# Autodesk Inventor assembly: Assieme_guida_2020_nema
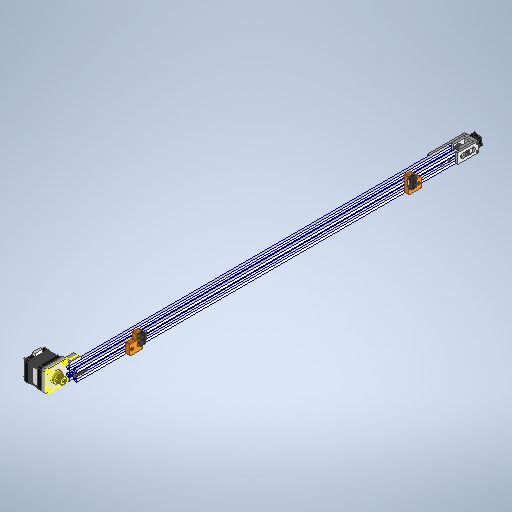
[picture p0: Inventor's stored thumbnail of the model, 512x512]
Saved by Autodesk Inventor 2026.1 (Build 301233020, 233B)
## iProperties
Created: 2026-01
Part Number: Assieme_guida_2020_nema
Document SubType Name: Assembly
Designer: hp
Sending System: Autodesk Inventor 2025
Preprocessor: ST-DEVELOPER v20
Title: Assieme_guida_2020_nema.stp
Author: R5800u
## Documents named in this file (17)
- C:\Users\hp\Documents\Inventor\DOM1_CartesianRobot\Assieme_guida_2020_nema - Copy.iam
- C:\Users\hp\Documents\Inventor\DOM1_CartesianRobot\2020 Belt Tensioner G_K.iam
- C:\Users\hp\Documents\Inventor\DOM1_CartesianRobot\GT2_20T.ipt
- C:\Users\hp\Documents\Inventor\DOM1_CartesianRobot\NO-NC Limit Switch.ipt
- C:\Users\hp\Documents\Inventor\DOM1_CartesianRobot\blocco_sensore.ipt
- C:\Users\hp\Documents\Inventor\DOM1_CartesianRobot\blocco_sensore_MIR.ipt
- C:\Users\hp\Documents\Inventor\DOM1_CartesianRobot\NEMA 42SHDC3030Z.ipt
- C:\Users\hp\Documents\Inventor\DOM1_CartesianRobot\blocco_nema.ipt
- C:\Users\hp\Documents\Inventor\DOM1_CartesianRobot\2020v2.ipt
- C:\Users\hp\Documents\Inventor\Content Center Files\R2026\en-US\ISO 4762(2)\ISO 4762 - M4 x 25ISO.ipt
- C:\Users\hp\Documents\Inventor\Content Center Files\R2026\en-US\ISO 4762(2)\ISO 4762 - M3 x 25ISO.ipt
- C:\Users\hp\Documents\Inventor\Content Center Files\R2021\en-US\ISO 4017(1)\ISO 4017 - M2 x 8 - ISO.ipt
- C:\Users\hp\Documents\Inventor\Content Center Files\R2026\en-US\ISO 4017(1)\ISO 4017 - M4 x 25 - ISO.ipt
- C:\Users\hp\Documents\Inventor\DOM1_CartesianRobot\2020 M4 (1).ipt
- C:\Users\hp\Documents\Inventor\Content Center Files\R2026\en-US\ANSI B18.3.1M(5)\ANSI B18.3.1M - M3x0.5 x 45(3).ipt
- C:\Users\hp\Documents\Inventor\Content Center Files\R2026\en-US\ISO 4032(2)\ISO 4032 - M3 - ISO.ipt
- C:\Users\hp\Documents\Inventor\DOM1_CartesianRobot\2020 M3.ipt
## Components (33 placed, 16 different names)
1. 2020:1
2. 2020 Belt Tensioner G_K:1 [sub-assembly]
3. GT2_20T:1 — Rigid:1
4. NO-NC Limit Switch:1 — Mate:9, Mate:10, Mate:11, Mate:36, Mate:37, Mate:38, Mate:39
5. NO-NC Limit Switch:2 — Mate:17, Mate:18, Mate:19
6. blocco_sensore:1
7. blocco_sensore_MIR:1
8. NEMA 42SHDC3030Z:1
9. blocco_nema:1
10. ISO 4762 M3 x 25:1 — Mate:32, Mate:33, Mate:76
11. ISO 4762 M3 x 25:2 — Mate:34, Mate:35, Mate:77
12. ISO 4017 M2 x 8:1 — Mate:36, Mate:37
13. ISO 4017 M2 x 8:2 — Mate:38, Mate:39
14. ISO 4017 M4 x 25:1 — Mate:40, Mate:41
15. ISO 4017 M4 x 25:2 — Mate:42, Mate:43
16. 2020 M4 (1):1 — Mate:44, Angle:1, Mate:51
17. 2020 M4 (1):2 — Mate:45, Angle:2, Mate:50
18. ISO 4762 M4 x 25:1 — Mate:46, Mate:47, Mate:50
19. ISO 4762 M4 x 25:2 — Mate:48, Mate:49, Mate:51
20. Drilled Forged Hexagon Socket Head Cap Screw - 6 Holes - Metric M3x0.5 x 45:1 — Mate:52, Mate:53
21. ISO 4032 M3:1 — Mate:60, Mate:61
22. Drilled Forged Hexagon Socket Head Cap Screw - 6 Holes - Metric M3x0.5 x 45:2 — Mate:54, Mate:55
23. Drilled Forged Hexagon Socket Head Cap Screw - 6 Holes - Metric M3x0.5 x 45:3 — Mate:56, Mate:57
24. Drilled Forged Hexagon Socket Head Cap Screw - 6 Holes - Metric M3x0.5 x 45:4 — Mate:58, Mate:59
25. ISO 4032 M3:2 — Mate:62, Mate:63
26. ISO 4032 M3:3 — Mate:64, Mate:65
27. ISO 4032 M3:4 — Mate:66, Mate:67
28. ISO 4762 M3 x 25:3 — Mate:68, Mate:69, Mate:79
29. ISO 4762 M3 x 25:4 — Mate:70, Mate:71, Mate:78
30. 2020 M3:1 — Mate:72, Angle:3, Mate:79
31. 2020 M3:2 — Mate:73, Angle:4, Mate:78
32. 2020 M3:5 — Mate:75, Angle:5, Mate:77
33. 2020 M3:6 — Mate:74, Angle:6, Mate:76
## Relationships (61: Mate 54, Angle 6, WeldJoint 1)
- Rigid:1 [WeldJoint]: GT2_20T:1
- Mate:9: NO-NC Limit Switch:1
- Mate:10: NO-NC Limit Switch:1
- Mate:11: NO-NC Limit Switch:1
- Mate:17: NO-NC Limit Switch:2
- Mate:18: NO-NC Limit Switch:2
- Mate:19: NO-NC Limit Switch:2
- Mate:32: ISO 4762 M3 x 25:1
- Mate:33: ISO 4762 M3 x 25:1
- Mate:34: ISO 4762 M3 x 25:2
- Mate:35: ISO 4762 M3 x 25:2
- Mate:36: NO-NC Limit Switch:1 ↔ ISO 4017 M2 x 8:1
- Mate:37: NO-NC Limit Switch:1 ↔ ISO 4017 M2 x 8:1
- Mate:38: NO-NC Limit Switch:1 ↔ ISO 4017 M2 x 8:2
- Mate:39: NO-NC Limit Switch:1 ↔ ISO 4017 M2 x 8:2
- Mate:40: ISO 4017 M4 x 25:1
- Mate:41: ISO 4017 M4 x 25:1
- Mate:42: ISO 4017 M4 x 25:2
- Mate:43: ISO 4017 M4 x 25:2
- Mate:44: 2020 M4 (1):1
- Mate:45: 2020 M4 (1):2
- Angle:1: 2020 M4 (1):1
- Angle:2: 2020 M4 (1):2
- Mate:46: ISO 4762 M4 x 25:1
- Mate:47: ISO 4762 M4 x 25:1
- Mate:48: ISO 4762 M4 x 25:2
- Mate:49: ISO 4762 M4 x 25:2
- Mate:50: 2020 M4 (1):2 ↔ ISO 4762 M4 x 25:1
- Mate:51: 2020 M4 (1):1 ↔ ISO 4762 M4 x 25:2
- Mate:52: Drilled Forged Hexagon Socket Head Cap Screw - 6 Holes - Metric M3x0.5 x 45:1
- Mate:53: Drilled Forged Hexagon Socket Head Cap Screw - 6 Holes - Metric M3x0.5 x 45:1
- Mate:54: Drilled Forged Hexagon Socket Head Cap Screw - 6 Holes - Metric M3x0.5 x 45:2
- Mate:55: Drilled Forged Hexagon Socket Head Cap Screw - 6 Holes - Metric M3x0.5 x 45:2
- Mate:56: Drilled Forged Hexagon Socket Head Cap Screw - 6 Holes - Metric M3x0.5 x 45:3
- Mate:57: Drilled Forged Hexagon Socket Head Cap Screw - 6 Holes - Metric M3x0.5 x 45:3
- Mate:58: Drilled Forged Hexagon Socket Head Cap Screw - 6 Holes - Metric M3x0.5 x 45:4
- Mate:59: Drilled Forged Hexagon Socket Head Cap Screw - 6 Holes - Metric M3x0.5 x 45:4
- Mate:60: ISO 4032 M3:1
- Mate:61: ISO 4032 M3:1
- Mate:62: ISO 4032 M3:2
- Mate:63: ISO 4032 M3:2
- Mate:64: ISO 4032 M3:3
- Mate:65: ISO 4032 M3:3
- Mate:66: ISO 4032 M3:4
- Mate:67: ISO 4032 M3:4
- Mate:68: ISO 4762 M3 x 25:3
- Mate:69: ISO 4762 M3 x 25:3
- Mate:70: ISO 4762 M3 x 25:4
- Mate:71: ISO 4762 M3 x 25:4
- Mate:72: 2020 M3:1
- Mate:73: 2020 M3:2
- Angle:3: 2020 M3:1
- Angle:4: 2020 M3:2
- Mate:74: 2020 M3:6
- Mate:75: 2020 M3:5
- Angle:5: 2020 M3:5
- Angle:6: 2020 M3:6
- Mate:76: ISO 4762 M3 x 25:1 ↔ 2020 M3:6
- Mate:77: ISO 4762 M3 x 25:2 ↔ 2020 M3:5
- Mate:78: ISO 4762 M3 x 25:4 ↔ 2020 M3:2
- Mate:79: ISO 4762 M3 x 25:3 ↔ 2020 M3:1
